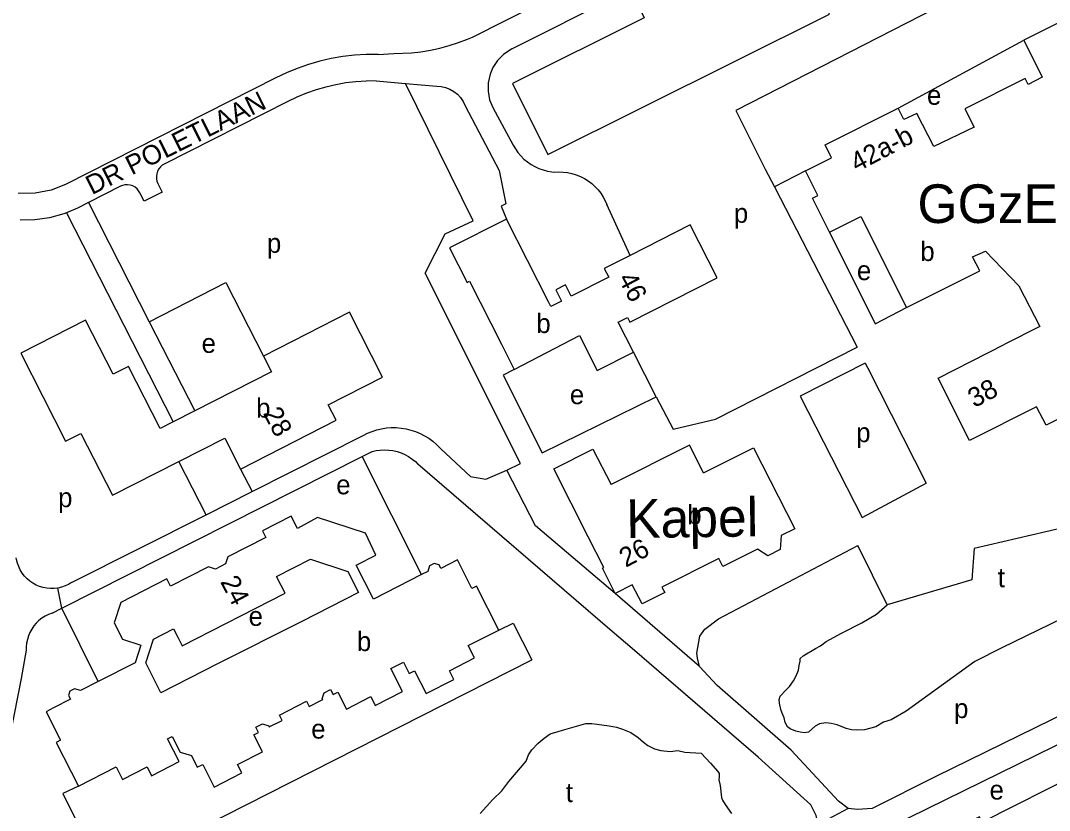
# Model space of a CAD drawing. Extents: x 158142 to 159655, y 385262 to 387204.
# Drawn here: x 158843.1 to 159056.3, y 386403.5 to 386567 of the extents above; entities that cross this region are included whole.
import ezdxf

# ---------------------------------------------------------------- set-up
doc = ezdxf.new("R2010")
doc.units = 0
for name, color, linetype in [('BLT_Basislijn', 7, 'Continuous'), ('BLT_Bebouwing', 7, 'Continuous'), ('BLT_Bebouwing_beschrifting', 7, 'Continuous'), ('BLT_Centroide', 7, 'Continuous'), ('BLT_Huisnummer', 7, 'Continuous'), ('BLT_Huisnummer_reeks', 7, 'Continuous'), ('BLT_Straatnaam_verkleind', 7, 'Continuous'), ('BLT_Terrein_beschrifting', 7, 'Continuous'), ('BLT_Vlakafsluiter', 7, 'Continuous')]:
    doc.layers.add(name, color=color, linetype=linetype)

msp = doc.modelspace()

# ---------------------------------------------------------------- linework, layer by layer
at = {"layer": 'BLT_Basislijn'}
for p, q in [((159024.99, 386548.9), (159051.01, 386562.95)), ((158916.85, 386554.52), (158922.91, 386553.98)), ((158940.99, 386549.04), (158945.22, 386541.24)), ((158991.36, 386548.38), (158997.47, 386536.25)), ((158997.47, 386536.25), (158999.35, 386532.59)), ((159005.81, 386535.92), (158999.35, 386532.59)), ((158863.82, 386532.71), (158857.21, 386529.36)), ((158999.35, 386532.59), (159016.49, 386499.36)), ((158854.91, 386528.2), (158852.68, 386527.24)), ((158857.21, 386529.36), (158854.91, 386528.2)), ((158857.21, 386529.36), (158869.8, 386504.66)), ((158942.72, 386528.6), (158943.87, 386525.92)), ((158969.48, 386518.4), (158964.63, 386528.93)), ((158852.68, 386527.24), (158874.76, 386483.93)), ((158869.8, 386504.66), (158879.22, 386486.2)), ((158974.88, 386489.12), (158970.13, 386498.34)), ((158891.1, 386469.51), (158914.11, 386481.11)), ((158851.67, 386445.35), (158913.9, 386476.74)), ((158913.9, 386476.74), (158915.97, 386477.78)), ((158926.23, 386452.32), (158913.9, 386476.74)), ((158881.57, 386464.7), (158875.97, 386475.73)), ((158965.76, 386440.55), (158925.48, 386475.17)), ((158943.9, 386473.92), (158946.73, 386475.31)), ((158888.74, 386474.15), (158891.1, 386469.51)), ((159017.51, 386464.14), (159030.79, 386471.27)), ((158881.57, 386464.7), (158891.1, 386469.51)), ((158853.73, 386450.67), (158881.57, 386464.7)), ((158983.8, 386433.29), (158966.34, 386448.38)), ((158849.67, 386444.34), (158851.67, 386445.35)), ((158859.24, 386430.17), (158851.67, 386445.35)), ((158942.22, 386440.82), (158945.19, 386442.25)), ((158945.19, 386442.25), (158949.09, 386434.63)), ((158969.85, 386437.02), (158965.76, 386440.55)), ((158844.33, 386436.69), (158843.29, 386430.77)), ((158855.14, 386408.52), (158851.89, 386406.97)), ((158851.89, 386406.97), (158858.34, 386394.06))]:
    msp.add_line(p, q, dxfattribs=at)
for points in [[(158936.78, 386563.59), (159005.02, 386598.11), (159005.43, 386605.04)], [(158944.95, 386561.15), (158966.73, 386572.16), (158967.88, 386572.49), (158969.02, 386572.33), (158970.07, 386571.73), (158970.76, 386570.82), (158972.38, 386567.56), (158945.07, 386553.98), (158952.37, 386539.31), (159010.75, 386568.35), (159003.45, 386583.02), (158976.14, 386569.43), (158974.5, 386572.74), (158974.17, 386573.92), (158974.34, 386575.03), (158974.87, 386575.98), (158975.83, 386576.76), (159007.51, 386593.32), (159013.57, 386595)], [(159052.99, 386577.13), (159045.69, 386573.45), (159044.58, 386575.63), (158991.36, 386548.38)], [(158917.21, 386560.01), (158920.52, 386560.18), (158924.12, 386560.33), (158926.1, 386560.57), (158928.08, 386560.89), (158930.03, 386561.32), (158931.96, 386561.84), (158933.86, 386562.45), (158935.74, 386563.15), (158936.78, 386563.59)], [(158917.21, 386560.01), (158914.79, 386559.99), (158912.37, 386559.84), (158909.94, 386559.55), (158907.53, 386559.14), (158905.14, 386558.59), (158902.79, 386557.92), (158900.48, 386557.12), (158898.23, 386556.2), (158896.04, 386555.17)], [(158944.95, 386561.15), (158943.25, 386560.01), (158942, 386558.78), (158941.02, 386557.3), (158940.46, 386555.92), (158940.03, 386554.12), (158940.01, 386552.37), (158940.34, 386550.63), (158940.99, 386549.04)], [(158896.04, 386555.17), (158852.43, 386533.1)], [(158916.85, 386554.52), (158914.75, 386554.49), (158912.65, 386554.35), (158910.55, 386554.09), (158908.47, 386553.72), (158906.4, 386553.24), (158904.37, 386552.66), (158902.37, 386551.96), (158900.42, 386551.16), (158898.52, 386550.27)], [(158946.73, 386475.31), (158927.01, 386514.71), (158931.11, 386522.84), (158936.96, 386525.53), (158922.91, 386553.98)], [(158922.91, 386553.98), (158929.37, 386553.4), (158930.31, 386553.34), (158931.23, 386553.15), (158932.11, 386552.8), (158932.93, 386552.33), (158933.67, 386551.75), (158934.3, 386551.06), (158934.83, 386550.28), (158935.28, 386549.35)], [(158898.52, 386550.27), (158872.92, 386537.31)], [(158935.28, 386549.35), (158942.35, 386535.94), (158943.68, 386529.07), (158942.72, 386528.6)], [(158945.22, 386541.24), (158945.68, 386540.45), (158946.21, 386539.7), (158946.8, 386538.99), (158947.46, 386538.35), (158948.16, 386537.76), (158948.92, 386537.23), (158949.72, 386536.78), (158950.55, 386536.39), (158951.42, 386536.08), (158952.3, 386535.84), (158953.21, 386535.69), (158953.76, 386535.63)], [(158872.92, 386537.31), (158872.51, 386537.06), (158872.13, 386536.72), (158871.79, 386536.31), (158871.53, 386535.83), (158871.36, 386535.31), (158871.28, 386534.78), (158871.3, 386534.25), (158871.41, 386533.75), (158871.59, 386533.3)], [(158953.76, 386535.63), (158954.68, 386535.68), (158955.6, 386535.64), (158956.51, 386535.53), (158957.41, 386535.34), (158958.29, 386535.07), (158959.15, 386534.72), (158959.97, 386534.3), (158960.75, 386533.82), (158961.49, 386533.26), (158962.17, 386532.65), (158962.8, 386531.98), (158963.37, 386531.25), (158963.87, 386530.48), (158964.31, 386529.67), (158964.63, 386528.93)], [(158852.43, 386533.1), (158849.49, 386531.93), (158846.18, 386531.26), (158842.64, 386531.24)], [(158867.86, 386531.36), (158867.61, 386531.78), (158867.28, 386532.17), (158866.86, 386532.51), (158866.38, 386532.78), (158865.85, 386532.95), (158865.31, 386533.02), (158864.78, 386533), (158864.27, 386532.89), (158863.82, 386532.71)], [(158871.59, 386533.3), (158872.5, 386531.48), (158868.72, 386529.64)], [(158868.72, 386529.64), (158867.86, 386531.36)], [(158852.68, 386527.24), (158852.11, 386527), (158849.15, 386526.17), (158846.11, 386525.73), (158843.07, 386525.7)], [(159010.76, 386523.17), (159020.22, 386504.23), (159026.71, 386507.58)], [(158869.8, 386504.66), (158885.68, 386512.8), (158893.49, 386497.55)], [(158974.88, 386489.12), (158978.35, 386482.4), (158987.17, 386484.47), (159016.49, 386499.36)], [(159018.19, 386496.06), (159004.67, 386489.27), (159017.51, 386464.14)], [(159018.19, 386496.06), (159018.72, 386495.02), (159030.79, 386471.27)], [(158945.44, 386494.76), (158943.17, 386493.58), (158951.2, 386477.54), (158974.88, 386489.12)], [(158914.11, 386481.11), (158915.02, 386481.57), (158915.97, 386481.96), (158916.95, 386482.27), (158917.94, 386482.5), (158918.95, 386482.66), (158919.97, 386482.73), (158921, 386482.73), (158922.02, 386482.65), (158923.03, 386482.48), (158924.02, 386482.24), (158924.99, 386481.92), (158925.94, 386481.53), (158926.85, 386481.06), (158927.72, 386480.53), (158928.55, 386479.93), (158929.32, 386479.26), (158930.05, 386478.54), (158930.24, 386478.33)], [(158915.97, 386477.78), (158916.82, 386477.98), (158917.69, 386478.1), (158918.56, 386478.14), (158919.43, 386478.1), (158920.3, 386477.98), (158921.15, 386477.78), (158921.98, 386477.51), (158922.79, 386477.16), (158923.55, 386476.73), (158924.27, 386476.24), (158924.95, 386475.69), (158925.48, 386475.17)], [(158930.24, 386478.33), (158936.38, 386472.62), (158939.58, 386472.07), (158943.9, 386473.92)], [(158966.34, 386448.38), (158949.82, 386462.42), (158943.9, 386473.92)], [(159061.51, 386462.57), (159040.75, 386457.72), (159040.28, 386451.19), (159022.7, 386446.02)], [(158983.8, 386433.29), (158983.39, 386434.98), (158983.25, 386436.02), (158983.88, 386439.59), (158984.93, 386440.99), (158987.8, 386443.16), (159016.61, 386458.34)], [(159022.7, 386446.02), (159016.61, 386458.34)], [(158850.89, 386449.52), (158850.13, 386449.43), (158849.36, 386449.41), (158848.59, 386449.47), (158847.83, 386449.62), (158847.09, 386449.84), (158846.38, 386450.14), (158845.71, 386450.5), (158845.07, 386450.94), (158844.49, 386451.44), (158843.96, 386452), (158843.49, 386452.61), (158843.08, 386453.26), (158842.75, 386453.96), (158842.49, 386454.68), (158842.3, 386455.43), (158842.24, 386455.77)], [(158853.73, 386450.67), (158853.07, 386450.27), (158852.37, 386449.95), (158851.64, 386449.69), (158850.89, 386449.52)], [(159108.26, 386447.42), (159032.81, 386410.48), (159019.6, 386403.88), (159016.58, 386403.67), (159014.61, 386403.9)], [(159061.51, 386444.44), (159046.5, 386437.11), (159040.91, 386434.28), (159026.64, 386424.01), (159023.53, 386422.21), (159021.96, 386421.76), (159020.4, 386420.76), (159018.05, 386420.14), (159016.43, 386420.12), (159015.35, 386420.18), (159014.24, 386420.45), (159012.35, 386421.18), (159011.1, 386421.49), (159010, 386421.59), (159008.69, 386421.43), (159007.83, 386420.93), (159006.4, 386419.7), (159005.56, 386419.56), (159004.72, 386419.66), (159003.81, 386419.92), (159002.62, 386420.36), (159002.09, 386420.76), (159001.57, 386421.65), (159001.35, 386422.67), (159000.96, 386423.62), (159000.71, 386424.39), (159000.41, 386425.69), (159000.37, 386426.46), (159000.56, 386427.14), (159001.7, 386428.38), (159002.46, 386429.11), (159003.29, 386430.28), (159003.89, 386431.36), (159004.32, 386432.52), (159004.51, 386433.48), (159004.66, 386434.36), (159004.71, 386434.95), (159005.29, 386435.49), (159007.9, 386436.99), (159008.94, 386437.59), (159010.07, 386438.43), (159013.24, 386440.15), (159017.45, 386442.34), (159020.51, 386444.12), (159022.7, 386446.02)], [(158849.67, 386444.34), (158848.94, 386444.07), (158848.23, 386443.72), (158847.57, 386443.3), (158846.96, 386442.81), (158846.39, 386442.27), (158845.89, 386441.67), (158845.45, 386441.02), (158845.07, 386440.33), (158844.77, 386439.61), (158844.55, 386438.86), (158844.4, 386438.09), (158844.33, 386437.31), (158844.33, 386436.69)], [(159008.44, 386400.57), (159008.02, 386402.46), (159006.91, 386404.66), (158996.01, 386414.53), (158969.85, 386437.02)], [(158858.34, 386394.06), (158860.47, 386393.36), (158876.54, 386401.57), (158880.9, 386400.07), (158949.09, 386434.63)], [(159014.61, 386403.9), (159012.62, 386405.39), (159002.82, 386415.93), (158987.48, 386429.35), (158983.8, 386433.29)], [(158843.29, 386430.77), (158837.33, 386400.92), (158837.2, 386395.94), (158837.65, 386388.99), (158838.18, 386387.27)], [(158938.41, 386402.84), (158940.98, 386405.71), (158942.89, 386407.52), (158944.31, 386409.48), (158947.89, 386413.66), (158948.4, 386414.98), (158949.09, 386416), (158950.37, 386417.4), (158951.67, 386418.42), (158952.88, 386419.36), (158954.53, 386419.85), (158955.44, 386420.07), (158960.31, 386421.47), (158961.5, 386421.45), (158963.62, 386421.2), (158965.12, 386420.96), (158966.61, 386420.7), (158967.88, 386420.29), (158969.57, 386419.59), (158971.13, 386418.55), (158972.2, 386417.61), (158973.12, 386416.9), (158974.51, 386416.24), (158975.82, 386415.91), (158977.76, 386415.67), (158979.32, 386415.86), (158980.76, 386415.57), (158984.21, 386415.36), (158986.11, 386413.24), (158987.61, 386411.53), (158987.91, 386411.15), (158987.94, 386410.46), (158987.87, 386409.8), (158988.09, 386408.65), (158988.39, 386406.18), (158988.59, 386405.61), (158989.13, 386404.73), (158990.46, 386402.85)], [(159023.64, 386400.21), (159061.09, 386418.61), (159063, 386418.33), (159065.21, 386414.36)]]:
    msp.add_lwpolyline(points, dxfattribs=at)
at = {"layer": 'BLT_Bebouwing'}
for p, q in [((159059.03, 386566.97), (159051.01, 386562.95)), ((158970.13, 386498.34), (158966.99, 386504.54)), ((159033.29, 386492.97), (159047.11, 386500)), ((158962.63, 386494.55), (158970.13, 386498.34)), ((159039.81, 386480.05), (159033.29, 386492.97)), ((158879.22, 386486.2), (158874.76, 386483.93)), ((158984.64, 386473.36), (158995.01, 386478.52)), ((158953.68, 386474.23), (158961.72, 386478.28)), ((158961.72, 386478.28), (158965.53, 386470.98)), ((158960.78, 386460.14), (158953.68, 386474.23))]:
    msp.add_line(p, q, dxfattribs=at)
for points in [[(159051.01, 386562.95), (159054.86, 386555.28), (159051.91, 386553.8), (159051.29, 386555.03), (159038.83, 386548.71)], [(159005.81, 386535.92), (159011.17, 386538.61), (159009.85, 386541.29), (159024.99, 386548.9)], [(159038.83, 386548.71), (159040.73, 386544.97), (159032.36, 386540.93), (159028.89, 386547.79), (159026.2, 386546.5), (159024.99, 386548.9)], [(159010.76, 386523.17), (159007.22, 386530.22), (159008.38, 386530.8), (159005.81, 386535.92)], [(158943.87, 386525.92), (158932.05, 386519.93), (158935.67, 386512.77), (158936.18, 386513.03), (158942.78, 386500), (158945.44, 386494.76)], [(158969.48, 386518.4), (158964.11, 386515.67), (158965.01, 386513.89), (158957.26, 386509.97), (158956.08, 386512.29), (158954.04, 386511.26), (158955.22, 386508.93), (158953.04, 386507.82), (158952.56, 386508.77), (158943.87, 386525.92)], [(159010.76, 386523.17), (159017.24, 386526.43), (159026.71, 386507.58)], [(158966.99, 386504.54), (158968.93, 386505.52), (158969.4, 386504.59), (158987.51, 386513.77), (158981.93, 386524.71), (158969.48, 386518.4)], [(159026.71, 386507.58), (159041.89, 386515.18), (159040.41, 386518.13), (159043.13, 386519.24), (159050.02, 386512.07)], [(159050.02, 386512.07), (159054.38, 386503.67), (159047.11, 386500)], [(158888.74, 386474.15), (158908.55, 386484.26), (158906.9, 386487.48), (158918.14, 386493.2), (158911.32, 386506.62), (158893.49, 386497.55)], [(158874.76, 386483.93), (158872.07, 386482.56), (158865.5, 386495.39), (158862.32, 386493.78), (158856.59, 386504.97), (158843.18, 386498.13), (158852.46, 386479.92), (158855.66, 386481.54), (158862.22, 386468.72), (158875.97, 386475.73)], [(158945.44, 386494.76), (158958.96, 386501.78), (158962.63, 386494.55)], [(159079.28, 386500), (159072.77, 386496.72), (159074.74, 386492.79), (159055.65, 386483.24), (159053.69, 386487.05), (159039.81, 386480.05)], [(158893.49, 386497.55), (158895.14, 386494.32), (158879.22, 386486.2)], [(158875.97, 386475.73), (158885.47, 386480.57), (158888.74, 386474.15)], [(158984.64, 386473.36), (158981.74, 386479.08), (158965.53, 386470.98)], [(158995.01, 386478.52), (159003.56, 386461.79), (159000.74, 386460.37), (159000.56, 386457.49), (158997.98, 386456.18), (158995.86, 386457.58), (158988.7, 386453.99), (158987.87, 386455.64), (158976.06, 386449.72), (158976.62, 386448.6), (158971.95, 386446.28)], [(158926.23, 386452.32), (158916.25, 386447.23), (158912.66, 386454.25), (158916.79, 386456.36), (158914.6, 386460.89), (158904.68, 386464.1), (158900.51, 386461.85), (158899.2, 386464.42), (158893.28, 386461.4), (158893.99, 386460), (158886.12, 386455.98), (158885.64, 386454.51), (158883.54, 386453.43), (158882.08, 386453.91), (158874.22, 386449.9), (158873.45, 386451.41), (158863.89, 386446.53), (158862.53, 386442.33), (158864.26, 386438.93), (158868.06, 386437.71), (158866.88, 386434.06), (158859.24, 386430.17)], [(158966.34, 386448.38), (158963.7, 386453.62), (158963.99, 386453.77), (158960.78, 386460.14)], [(158870.68, 386438.96), (158874.81, 386441.07), (158875.77, 386439.19), (158876.6, 386437.56), (158897.94, 386448.45), (158897.11, 386450.08), (158896.18, 386451.9), (158903.19, 386455.48), (158910.99, 386452.95), (158913.2, 386448.61), (158901.44, 386442.61), (158883.98, 386433.85), (158872.24, 386427.86), (158869.09, 386434.04), (158870.68, 386438.96)], [(158942.22, 386440.82), (158937.6, 386449.88), (158936.68, 386449.41), (158933.65, 386455.34), (158933.65, 386455.34), (158930.23, 386453.6), (158929.87, 386454.3), (158928.86, 386454.63), (158927.89, 386454.13), (158927.52, 386452.98), (158926.23, 386452.32)], [(158971.95, 386446.28), (158969.91, 386450.18), (158966.34, 386448.38)], [(158935.91, 386437.6), (158942.22, 386440.82)], [(158862.94, 386412.5), (158864.27, 386409.89), (158869.36, 386412.48), (158870.29, 386410.66), (158876.02, 386413.58), (158873.62, 386418.28), (158874.58, 386418.78), (158876.22, 386415.57), (158878.53, 386414.82), (158879.75, 386412.43), (158880.88, 386413), (158883.28, 386408.31), (158889.02, 386411.24), (158888.12, 386413), (158893.3, 386415.64), (158891.51, 386419.14), (158892.43, 386419.61), (158891.88, 386420.7), (158893.27, 386421.41), (158894.59, 386420.98), (158894.69, 386420.76), (158897.37, 386422.13), (158896.82, 386423.21), (158902.42, 386426.07), (158902.96, 386425.01), (158905.75, 386426.44), (158905.67, 386426.6), (158906.08, 386427.84), (158907.4, 386428.52), (158907.94, 386427.47), (158908.88, 386427.95), (158910.65, 386424.47), (158915.7, 386427.04), (158916.62, 386425.23), (158922.3, 386428.13), (158919.87, 386432.88), (158922.46, 386434.21), (158923.69, 386431.81), (158924.79, 386432.37), (158927.19, 386427.68), (158932.92, 386430.6), (158932, 386432.39), (158937.21, 386435.05), (158935.91, 386437.6)], [(158859.24, 386430.17), (158855.54, 386428.28), (158854.31, 386428.67), (158853.34, 386428.18), (158853.05, 386427.28), (158853.46, 386426.49), (158850, 386424.72), (158848.44, 386423.92), (158851.44, 386418.04), (158850.52, 386417.57), (158855.14, 386408.52)], [(158855.14, 386408.52), (158862.94, 386412.5)], [(159065.21, 386414.36), (159061.96, 386412.72), (159062.67, 386411.27), (159042.43, 386401.06), (159041.88, 386402.15), (159035.14, 386398.75)]]:
    msp.add_lwpolyline(points, dxfattribs=at)
at = {"layer": 'BLT_Vlakafsluiter'}
for p, q in [((158851.67, 386445.35), (158850.89, 386449.52)), ((159014.61, 386403.9), (159008.44, 386400.57))]:
    msp.add_line(p, q, dxfattribs=at)

# ---------------------------------------------------------------- texts
at = {"layer": 'BLT_Bebouwing_beschrifting'}
msp.add_text('GGzE', height=8, dxfattribs=at).set_placement((159029, 386525.1))
at = {"layer": 'BLT_Centroide'}
for s, p in [('e', (159030.97, 386549.58)), ('p', (158990.95, 386525.14)), ('p', (158894.19, 386518.93)), ('b', (159029.59, 386517.23)), ('e', (159016.45, 386513.28)), ('b', (158950.02, 386502.32)), ('e', (158880.66, 386498.21)), ('e', (158956.97, 386487.59)), ('b', (158891.96, 386484.81)), ('p', (159016.3, 386479.73)), ('e', (158908.55, 386468.93)), ('p', (158850.92, 386466.27)), ('b', (158981.3, 386462.69)), ('t', (159045.64, 386449.69)), ('e', (158890.4, 386441.69)), ('b', (158912.84, 386436.47)), ('p', (159036.59, 386422.6)), ('e', (158903.37, 386418.35)), ('t', (158956.13, 386405.21)), ('e', (159043.94, 386405.73))]:
    msp.add_text(s, height=4, dxfattribs=at).set_placement(p)
at = {"layer": 'BLT_Huisnummer'}
for s, rotation, p in [('46', 297.8252, (158966.86, 386513.62)), ('28', 297.8252, (158893.31, 386485.73)), ('26', 27.8253, (158968.55, 386453.7)), ('24', 297.8252, (158884.45, 386450.81))]:
    msp.add_text(s, height=4, rotation=rotation, dxfattribs=at).set_placement(p)
at = {"layer": 'BLT_Huisnummer_reeks'}
for s, p in [('42a-b', (159016.44, 386535.56)), ('38', (159040.78, 386486.76))]:
    msp.add_text(s, height=4, rotation=27.8253, dxfattribs=at).set_placement(p)
at = {"layer": 'BLT_Straatnaam_verkleind'}
msp.add_text('DR POLETLAAN', height=4, rotation=26.407, dxfattribs=at).set_placement((158857.92, 386530.85))
at = {"layer": 'BLT_Terrein_beschrifting'}
msp.add_text('Kapel', height=8, rotation=0.7953, dxfattribs=at).set_placement((158968.69, 386459.85))

doc.saveas('drawing.dxf')
